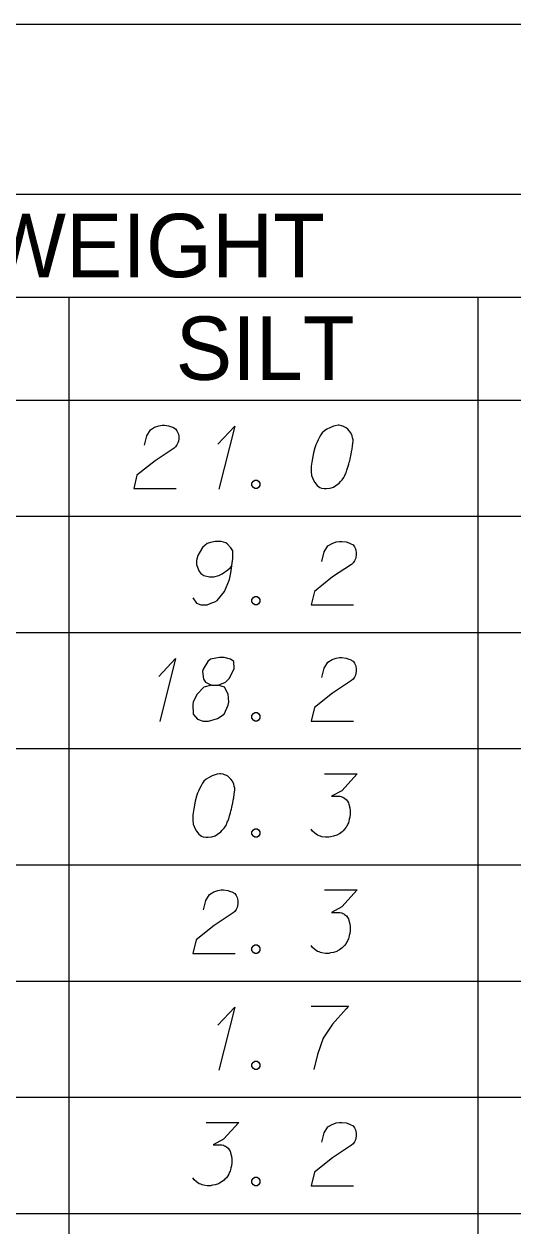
# Model space of a CAD drawing. Extents: x 2074207 to 2076812, y 516372 to 523312.
# Drawn here: x 2076584.7 to 2076621.8, y 518077.5 to 518168.6 of the extents above; entities that cross this region are included whole.
import ezdxf

# ---------------------------------------------------------------- set-up
doc = ezdxf.new("R2010")
doc.units = 0
for name, color, linetype in [('Prop DirtTable_ Soil Test Results - Outline (Major)', 7, 'Continuous'), ('Prop DirtTable_ Soil Test Results - Outline (Minor)', 7, 'Continuous'), ('Prop DirtTable_ Soil Test Results - Tx (Header - Small)', 7, 'Continuous'), ('Prop DirtTable_ Soil Test Results - Tx (Sample Data)', 7, 'Continuous')]:
    doc.layers.add(name, color=color, linetype=linetype)

msp = doc.modelspace()

# ---------------------------------------------------------------- linework, layer by layer
at = {"layer": 'Prop DirtTable_ Soil Test Results - Outline (Major)'}
for p, q in [((2076260.609, 518168.566), (2076811.903, 518168.566)), ((2076260.609, 518140.08), (2076811.903, 518140.08)), ((2076260.609, 518140.08), (2076811.903, 518140.08))]:
    msp.add_line(p, q, dxfattribs=at)
at = {"layer": 'Prop DirtTable_ Soil Test Results - Outline (Minor)'}
for p, q in [((2076260.609, 518155.68), (2076811.903, 518155.68)), ((2076526.074, 518147.88), (2076731.93, 518147.88)), ((2076588.114, 518147.88), (2076588.114, 518131.28)), ((2076619.134, 518131.28), (2076619.134, 518147.88)), ((2076260.609, 518131.28), (2076811.903, 518131.28)), ((2076260.609, 518131.28), (2076811.903, 518131.28)), ((2076588.114, 518131.28), (2076588.114, 518122.48)), ((2076619.134, 518122.48), (2076619.134, 518131.28)), ((2076260.609, 518122.48), (2076811.903, 518122.48)), ((2076260.609, 518122.48), (2076811.903, 518122.48)), ((2076588.114, 518122.48), (2076588.114, 518113.68)), ((2076619.134, 518113.68), (2076619.134, 518122.48)), ((2076260.609, 518113.68), (2076811.903, 518113.68)), ((2076260.609, 518113.68), (2076811.903, 518113.68)), ((2076588.114, 518113.68), (2076588.114, 518104.88)), ((2076619.134, 518104.88), (2076619.134, 518113.68)), ((2076260.609, 518104.88), (2076811.903, 518104.88)), ((2076260.609, 518104.88), (2076811.903, 518104.88)), ((2076588.114, 518104.88), (2076588.114, 518096.08)), ((2076619.134, 518096.08), (2076619.134, 518104.88)), ((2076260.609, 518096.08), (2076811.903, 518096.08)), ((2076260.609, 518096.08), (2076811.903, 518096.08)), ((2076588.114, 518096.08), (2076588.114, 518087.28)), ((2076619.134, 518087.28), (2076619.134, 518096.08)), ((2076260.609, 518087.28), (2076811.903, 518087.28)), ((2076260.609, 518087.28), (2076811.903, 518087.28)), ((2076588.114, 518087.28), (2076588.114, 518078.48)), ((2076619.134, 518078.48), (2076619.134, 518087.28)), ((2076260.609, 518078.48), (2076811.903, 518078.48)), ((2076260.609, 518078.48), (2076811.903, 518078.48)), ((2076588.114, 518078.48), (2076588.114, 518069.68)), ((2076619.134, 518069.68), (2076619.134, 518078.48))]:
    msp.add_line(p, q, dxfattribs=at)
at = {"layer": 'Prop DirtTable_ Soil Test Results - Tx (Sample Data)'}
for points in [[(2076593.847, 518136.663), (2076594.023, 518137.381), (2076594.306, 518137.835), (2076594.623, 518138.024), (2076594.94, 518138.137), (2076595.187, 518138.175), (2076595.364, 518138.175), (2076595.681, 518138.137), (2076595.893, 518138.062), (2076595.999, 518138.024), (2076596.21, 518137.911), (2076596.316, 518137.759), (2076596.387, 518137.608), (2076596.422, 518137.495), (2076596.457, 518137.344), (2076596.457, 518137.155), (2076596.422, 518136.966), (2076596.387, 518136.852), (2076596.316, 518136.701), (2076596.21, 518136.55), (2076596.105, 518136.437), (2076594.658, 518135.492), (2076593.283, 518134.396), (2076593.036, 518133.375), (2076596.246, 518133.375)], [(2076599.42, 518136.739), (2076600.69, 518138.1), (2076599.491, 518133.337)], [(2076608.592, 518138.175), (2076608.522, 518138.175), (2076608.31, 518138.137), (2076608.169, 518138.1), (2076608.063, 518138.062), (2076607.887, 518137.986), (2076607.675, 518137.873), (2076607.499, 518137.759), (2076607.322, 518137.608), (2076607.216, 518137.457), (2076607.111, 518137.268), (2076607.005, 518137.079), (2076606.899, 518136.852), (2076606.828, 518136.701), (2076606.758, 518136.474), (2076606.652, 518136.096), (2076606.546, 518135.529), (2076606.476, 518135.076), (2076606.476, 518134.66), (2076606.511, 518134.358), (2076606.652, 518134.018), (2076606.758, 518133.829), (2076606.934, 518133.602), (2076607.146, 518133.451), (2076607.252, 518133.413), (2076607.463, 518133.375), (2076607.64, 518133.375), (2076607.922, 518133.413), (2076608.169, 518133.489), (2076608.345, 518133.602), (2076608.592, 518133.791), (2076608.698, 518133.904), (2076608.839, 518134.055), (2076608.945, 518134.207), (2076609.015, 518134.32), (2076609.086, 518134.509), (2076609.121, 518134.585), (2076609.192, 518134.774), (2076609.262, 518135), (2076609.333, 518135.227), (2076609.368, 518135.378), (2076609.403, 518135.492), (2076609.439, 518135.643), (2076609.509, 518135.983), (2076609.545, 518136.172), (2076609.58, 518136.361), (2076609.615, 518136.626), (2076609.65, 518136.966), (2076609.65, 518137.079), (2076609.615, 518137.23), (2076609.58, 518137.381), (2076609.474, 518137.608), (2076609.368, 518137.759), (2076609.262, 518137.873), (2076609.121, 518137.986), (2076608.98, 518138.062), (2076608.874, 518138.1), (2076608.769, 518138.137), (2076608.592, 518138.175)], [(2076602.207, 518134.018), (2076602.384, 518134.018), (2076602.489, 518133.942), (2076602.595, 518133.791), (2076602.595, 518133.602), (2076602.489, 518133.451), (2076602.384, 518133.375), (2076602.207, 518133.375), (2076602.101, 518133.451), (2076601.996, 518133.602), (2076601.996, 518133.791), (2076602.101, 518133.942), (2076602.207, 518134.018)], [(2076597.516, 518125.104), (2076597.798, 518124.689), (2076598.115, 518124.575), (2076598.609, 518124.575), (2076598.962, 518124.726), (2076599.174, 518124.802), (2076599.35, 518124.915), (2076599.914, 518125.596), (2076600.302, 518126.503), (2076600.408, 518126.994), (2076600.549, 518128.09), (2076600.549, 518128.657), (2076600.408, 518128.884), (2076600.126, 518129.186), (2076600.02, 518129.262), (2076599.667, 518129.375), (2076599.209, 518129.375), (2076598.856, 518129.3), (2076598.609, 518129.224), (2076598.256, 518128.922), (2076597.904, 518128.317), (2076597.798, 518127.939), (2076597.798, 518127.637), (2076597.974, 518127.145), (2076598.115, 518126.956), (2076598.362, 518126.805), (2076598.786, 518126.692), (2076599.103, 518126.692), (2076599.491, 518126.805), (2076599.738, 518126.918), (2076600.161, 518127.221), (2076600.373, 518127.41), (2076600.479, 518127.523)], [(2076607.287, 518127.863), (2076607.463, 518128.581), (2076607.746, 518129.035), (2076608.063, 518129.224), (2076608.38, 518129.337), (2076608.627, 518129.375), (2076608.804, 518129.375), (2076609.121, 518129.337), (2076609.333, 518129.262), (2076609.439, 518129.224), (2076609.65, 518129.111), (2076609.756, 518128.959), (2076609.827, 518128.808), (2076609.862, 518128.695), (2076609.897, 518128.544), (2076609.897, 518128.355), (2076609.862, 518128.166), (2076609.827, 518128.052), (2076609.756, 518127.901), (2076609.65, 518127.75), (2076609.545, 518127.637), (2076608.098, 518126.692), (2076606.723, 518125.596), (2076606.476, 518124.575), (2076609.686, 518124.575)], [(2076602.207, 518125.218), (2076602.384, 518125.218), (2076602.489, 518125.142), (2076602.595, 518124.991), (2076602.595, 518124.802), (2076602.489, 518124.651), (2076602.384, 518124.575), (2076602.207, 518124.575), (2076602.101, 518124.651), (2076601.996, 518124.802), (2076601.996, 518124.991), (2076602.101, 518125.142), (2076602.207, 518125.218)], [(2076594.94, 518119.139), (2076596.21, 518120.5), (2076595.011, 518115.737)], [(2076598.927, 518118.496), (2076599.42, 518118.496), (2076599.562, 518118.534), (2076599.985, 518118.723), (2076600.302, 518119.026), (2076600.655, 518119.744), (2076600.62, 518120.273), (2076600.373, 518120.462), (2076599.879, 518120.575), (2076599.526, 518120.575), (2076598.856, 518120.462), (2076598.644, 518120.273), (2076598.292, 518119.706), (2076598.256, 518119.517), (2076598.327, 518118.95), (2076598.468, 518118.723), (2076598.927, 518118.496), (2076598.362, 518118.345), (2076597.833, 518117.778), (2076597.551, 518117.211), (2076597.516, 518117.022), (2076597.551, 518116.304), (2076597.868, 518115.926), (2076598.292, 518115.775), (2076598.715, 518115.775), (2076599.385, 518115.964), (2076599.879, 518116.304), (2076600.197, 518116.985), (2076600.232, 518117.211), (2076600.197, 518117.816), (2076599.914, 518118.345), (2076599.42, 518118.496)], [(2076607.287, 518119.063), (2076607.463, 518119.781), (2076607.746, 518120.235), (2076608.063, 518120.424), (2076608.38, 518120.537), (2076608.627, 518120.575), (2076608.804, 518120.575), (2076609.121, 518120.537), (2076609.333, 518120.462), (2076609.439, 518120.424), (2076609.65, 518120.311), (2076609.756, 518120.159), (2076609.827, 518120.008), (2076609.862, 518119.895), (2076609.897, 518119.744), (2076609.897, 518119.555), (2076609.862, 518119.366), (2076609.827, 518119.252), (2076609.756, 518119.101), (2076609.65, 518118.95), (2076609.545, 518118.837), (2076608.098, 518117.892), (2076606.723, 518116.796), (2076606.476, 518115.775), (2076609.686, 518115.775)], [(2076602.207, 518116.418), (2076602.384, 518116.418), (2076602.489, 518116.342), (2076602.595, 518116.191), (2076602.595, 518116.002), (2076602.489, 518115.851), (2076602.384, 518115.775), (2076602.207, 518115.775), (2076602.101, 518115.851), (2076601.996, 518116.002), (2076601.996, 518116.191), (2076602.101, 518116.342), (2076602.207, 518116.418)], [(2076599.632, 518111.775), (2076599.562, 518111.775), (2076599.35, 518111.737), (2076599.209, 518111.7), (2076599.103, 518111.662), (2076598.927, 518111.586), (2076598.715, 518111.473), (2076598.539, 518111.359), (2076598.362, 518111.208), (2076598.256, 518111.057), (2076598.151, 518110.868), (2076598.045, 518110.679), (2076597.939, 518110.452), (2076597.868, 518110.301), (2076597.798, 518110.074), (2076597.692, 518109.696), (2076597.586, 518109.129), (2076597.516, 518108.676), (2076597.516, 518108.26), (2076597.551, 518107.958), (2076597.692, 518107.618), (2076597.798, 518107.429), (2076597.974, 518107.202), (2076598.186, 518107.051), (2076598.292, 518107.013), (2076598.503, 518106.975), (2076598.68, 518106.975), (2076598.962, 518107.013), (2076599.209, 518107.089), (2076599.385, 518107.202), (2076599.632, 518107.391), (2076599.738, 518107.504), (2076599.879, 518107.655), (2076599.985, 518107.807), (2076600.055, 518107.92), (2076600.126, 518108.109), (2076600.161, 518108.185), (2076600.232, 518108.374), (2076600.302, 518108.6), (2076600.373, 518108.827), (2076600.408, 518108.978), (2076600.443, 518109.092), (2076600.479, 518109.243), (2076600.549, 518109.583), (2076600.585, 518109.772), (2076600.62, 518109.961), (2076600.655, 518110.226), (2076600.69, 518110.566), (2076600.69, 518110.679), (2076600.655, 518110.83), (2076600.62, 518110.981), (2076600.514, 518111.208), (2076600.408, 518111.359), (2076600.302, 518111.473), (2076600.161, 518111.586), (2076600.02, 518111.662), (2076599.914, 518111.7), (2076599.809, 518111.737), (2076599.632, 518111.775)], [(2076607.499, 518111.775), (2076609.968, 518111.775), (2076608.804, 518110.49), (2076608.028, 518110.074), (2076608.663, 518110.074), (2076608.804, 518110.037), (2076608.874, 518109.999), (2076608.945, 518109.961), (2076609.015, 518109.923), (2076609.157, 518109.81), (2076609.227, 518109.696), (2076609.298, 518109.583), (2076609.333, 518109.47), (2076609.403, 518109.205), (2076609.439, 518108.978), (2076609.439, 518108.865), (2076609.439, 518108.714), (2076609.403, 518108.487), (2076609.368, 518108.336), (2076609.333, 518108.185), (2076609.298, 518108.071), (2076609.262, 518107.996), (2076609.227, 518107.92), (2076609.192, 518107.844), (2076609.121, 518107.731), (2076609.015, 518107.58), (2076608.91, 518107.466), (2076608.839, 518107.391), (2076608.733, 518107.315), (2076608.627, 518107.24), (2076608.486, 518107.164), (2076608.416, 518107.126), (2076608.169, 518107.051), (2076607.957, 518107.013), (2076607.816, 518106.975), (2076607.569, 518106.975), (2076607.287, 518107.013), (2076607.181, 518107.051), (2076607.075, 518107.089), (2076606.969, 518107.126), (2076606.864, 518107.202), (2076606.758, 518107.278), (2076606.581, 518107.429), (2076606.476, 518107.58)], [(2076602.207, 518107.618), (2076602.384, 518107.618), (2076602.489, 518107.542), (2076602.595, 518107.391), (2076602.595, 518107.202), (2076602.489, 518107.051), (2076602.384, 518106.975), (2076602.207, 518106.975), (2076602.101, 518107.051), (2076601.996, 518107.202), (2076601.996, 518107.391), (2076602.101, 518107.542), (2076602.207, 518107.618)], [(2076598.327, 518101.463), (2076598.503, 518102.181), (2076598.786, 518102.635), (2076599.103, 518102.824), (2076599.42, 518102.937), (2076599.667, 518102.975), (2076599.844, 518102.975), (2076600.161, 518102.937), (2076600.373, 518102.862), (2076600.479, 518102.824), (2076600.69, 518102.711), (2076600.796, 518102.559), (2076600.867, 518102.408), (2076600.902, 518102.295), (2076600.937, 518102.144), (2076600.937, 518101.955), (2076600.902, 518101.766), (2076600.867, 518101.652), (2076600.796, 518101.501), (2076600.69, 518101.35), (2076600.585, 518101.237), (2076599.138, 518100.292), (2076597.763, 518099.196), (2076597.516, 518098.175), (2076600.726, 518098.175)], [(2076607.499, 518102.975), (2076609.968, 518102.975), (2076608.804, 518101.69), (2076608.028, 518101.274), (2076608.663, 518101.274), (2076608.804, 518101.237), (2076608.874, 518101.199), (2076608.945, 518101.161), (2076609.015, 518101.123), (2076609.157, 518101.01), (2076609.227, 518100.896), (2076609.298, 518100.783), (2076609.333, 518100.67), (2076609.403, 518100.405), (2076609.439, 518100.178), (2076609.439, 518100.065), (2076609.439, 518099.914), (2076609.403, 518099.687), (2076609.368, 518099.536), (2076609.333, 518099.385), (2076609.298, 518099.271), (2076609.262, 518099.196), (2076609.227, 518099.12), (2076609.192, 518099.044), (2076609.121, 518098.931), (2076609.015, 518098.78), (2076608.91, 518098.666), (2076608.839, 518098.591), (2076608.733, 518098.515), (2076608.627, 518098.44), (2076608.486, 518098.364), (2076608.416, 518098.326), (2076608.169, 518098.251), (2076607.957, 518098.213), (2076607.816, 518098.175), (2076607.569, 518098.175), (2076607.287, 518098.213), (2076607.181, 518098.251), (2076607.075, 518098.289), (2076606.969, 518098.326), (2076606.864, 518098.402), (2076606.758, 518098.478), (2076606.581, 518098.629), (2076606.476, 518098.78)], [(2076602.207, 518098.818), (2076602.384, 518098.818), (2076602.489, 518098.742), (2076602.595, 518098.591), (2076602.595, 518098.402), (2076602.489, 518098.251), (2076602.384, 518098.175), (2076602.207, 518098.175), (2076602.101, 518098.251), (2076601.996, 518098.402), (2076601.996, 518098.591), (2076602.101, 518098.742), (2076602.207, 518098.818)], [(2076599.42, 518092.739), (2076600.69, 518094.1), (2076599.491, 518089.337)], [(2076606.476, 518094.175), (2076609.298, 518094.175), (2076609.121, 518093.986), (2076608.098, 518092.815), (2076607.393, 518091.756), (2076606.969, 518090.509), (2076606.687, 518089.375)], [(2076602.207, 518090.018), (2076602.384, 518090.018), (2076602.489, 518089.942), (2076602.595, 518089.791), (2076602.595, 518089.602), (2076602.489, 518089.451), (2076602.384, 518089.375), (2076602.207, 518089.375), (2076602.101, 518089.451), (2076601.996, 518089.602), (2076601.996, 518089.791), (2076602.101, 518089.942), (2076602.207, 518090.018)], [(2076598.539, 518085.375), (2076601.008, 518085.375), (2076599.844, 518084.09), (2076599.068, 518083.674), (2076599.703, 518083.674), (2076599.844, 518083.637), (2076599.914, 518083.599), (2076599.985, 518083.561), (2076600.055, 518083.523), (2076600.197, 518083.41), (2076600.267, 518083.296), (2076600.338, 518083.183), (2076600.373, 518083.07), (2076600.443, 518082.805), (2076600.479, 518082.578), (2076600.479, 518082.465), (2076600.479, 518082.314), (2076600.443, 518082.087), (2076600.408, 518081.936), (2076600.373, 518081.785), (2076600.338, 518081.671), (2076600.302, 518081.596), (2076600.267, 518081.52), (2076600.232, 518081.444), (2076600.161, 518081.331), (2076600.055, 518081.18), (2076599.95, 518081.066), (2076599.879, 518080.991), (2076599.773, 518080.915), (2076599.667, 518080.84), (2076599.526, 518080.764), (2076599.456, 518080.726), (2076599.209, 518080.651), (2076598.997, 518080.613), (2076598.856, 518080.575), (2076598.609, 518080.575), (2076598.327, 518080.613), (2076598.221, 518080.651), (2076598.115, 518080.689), (2076598.009, 518080.726), (2076597.904, 518080.802), (2076597.798, 518080.878), (2076597.621, 518081.029), (2076597.516, 518081.18)], [(2076607.287, 518083.863), (2076607.463, 518084.581), (2076607.746, 518085.035), (2076608.063, 518085.224), (2076608.38, 518085.337), (2076608.627, 518085.375), (2076608.804, 518085.375), (2076609.121, 518085.337), (2076609.333, 518085.262), (2076609.439, 518085.224), (2076609.65, 518085.111), (2076609.756, 518084.959), (2076609.827, 518084.808), (2076609.862, 518084.695), (2076609.897, 518084.544), (2076609.897, 518084.355), (2076609.862, 518084.166), (2076609.827, 518084.052), (2076609.756, 518083.901), (2076609.65, 518083.75), (2076609.545, 518083.637), (2076608.098, 518082.692), (2076606.723, 518081.596), (2076606.476, 518080.575), (2076609.686, 518080.575)], [(2076602.207, 518081.218), (2076602.384, 518081.218), (2076602.489, 518081.142), (2076602.595, 518080.991), (2076602.595, 518080.802), (2076602.489, 518080.651), (2076602.384, 518080.575), (2076602.207, 518080.575), (2076602.101, 518080.651), (2076601.996, 518080.802), (2076601.996, 518080.991), (2076602.101, 518081.142), (2076602.207, 518081.218)]]:
    msp.add_lwpolyline(points, dxfattribs=at)

# ---------------------------------------------------------------- texts
at = {"layer": 'Prop DirtTable_ Soil Test Results - Tx (Header - Small)'}
for s, height, p in [('% BY WEIGHT', 4.79998, (2076564.009, 518149.391)), ('SILT', 4.8, (2076596.215, 518141.616))]:
    msp.add_text(s, height=height, dxfattribs=at).set_placement(p)

doc.saveas('drawing.dxf')
